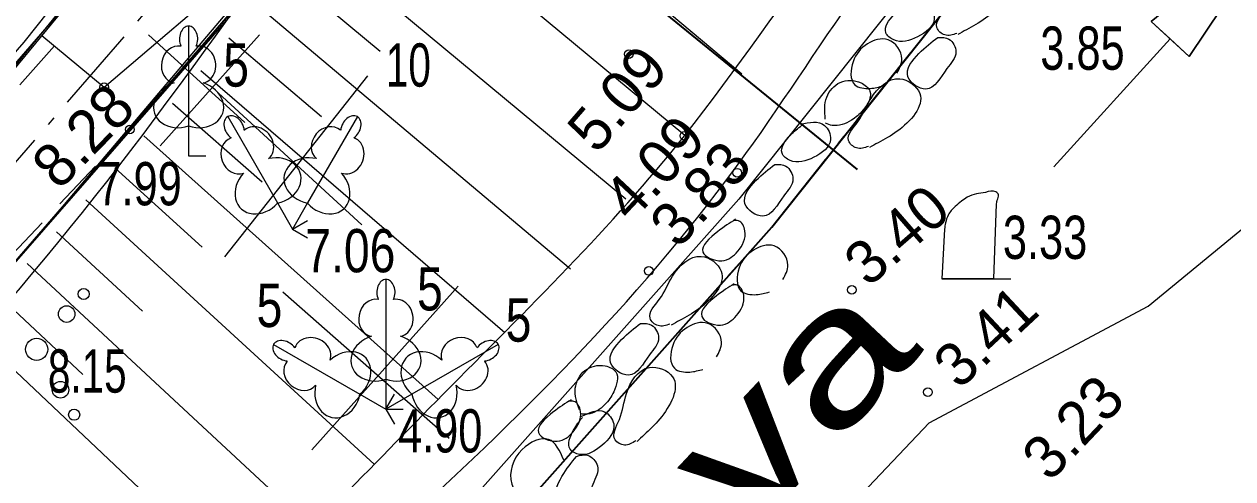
# Model space of a CAD drawing. Extents: x 514052 to 514314, y 297701 to 297876.
# Drawn here: x 514248.88 to 514262.86, y 297791.45 to 297796.71 of the extents above; entities that cross this region are included whole.
import ezdxf

# ---------------------------------------------------------------- set-up
doc = ezdxf.new("R2010")
doc.units = 0
doc.header["$LTSCALE"] = 0.2
doc.linetypes.add('DOT_DASHED', pattern=[7.7, 5, -1.2, 0.3, -1.2])
doc.linetypes.add('MEDIUM_DASHED', pattern=[4.5, 3, -1.5])
for name, color, linetype, lineweight in [('1', 7, 'Continuous', 13), ('19', 7, 'Continuous', 25), ('35', 7, 'Continuous', 25), ('4', 7, 'Continuous', 13), ('5', 7, 'Continuous', 13), ('55', 7, 'Continuous', 13), ('56', 7, 'Continuous', 13), ('6', 7, 'Continuous', 13), ('61', 7, 'Continuous', 13), ('62', 7, 'Continuous', 13), ('63', 7, 'Continuous', 13)]:
    doc.layers.add(name, color=color, linetype=linetype, lineweight=lineweight)
for name, color, linetype in [('12', 7, 'Continuous'), ('27', 7, 'Continuous'), ('8', 7, 'Continuous')]:
    doc.layers.add(name, color=color, linetype=linetype)

msp = doc.modelspace()

# ---------------------------------------------------------------- linework, layer by layer
at = {"layer": '1'}
for p, q in [((514253.484, 297799.238), (514257.177, 297796.134)), ((514252.844, 297798.47), (514256.52, 297795.422)), ((514252.206, 297797.701), (514255.837, 297794.686)), ((514251.886, 297797.316), (514252.993, 297796.394)), ((514251.565, 297796.933), (514255.194, 297793.878)), ((514251.243, 297796.55), (514252.317, 297795.641)), ((514250.918, 297796.17), (514254.438, 297793.143)), ((514250.59, 297795.792), (514251.63, 297794.884)), ((514250.26, 297795.418), (514253.663, 297792.368)), ((514249.925, 297795.046), (514250.935, 297794.13)), ((514249.588, 297794.676), (514252.926, 297791.62)), ((514249.25, 297794.308), (514250.245, 297793.391)), ((514248.911, 297793.941), (514252.207, 297790.881)), ((514248.57, 297793.575), (514249.554, 297792.656)), ((514248.228, 297793.211), (514251.49, 297790.135))]:
    msp.add_line(p, q, dxfattribs=at)
msp.add_spline([(514260.862, 297805.466), (514258.749, 297804.839), (514257.459, 297803.011), (514254.953, 297800.933), (514250.105, 297795.245), (514240.136, 297784.718), (514236.07, 297778.812), (514235.246, 297774.955), (514233.92, 297771.109), (514234.456, 297764.804)], degree=3, dxfattribs=at)
at = {"layer": '19', "lineweight": 13}
msp.add_spline([(514243.205, 297765.058), (514242.936, 297773.769), (514245.025, 297781.038), (514246.54, 297783.925), (514249.054, 297787.013), (514257.225, 297795.21), (514260.154, 297798.886), (514267.863, 297801.516), (514273.305, 297805.826), (514276.583, 297807.615)], degree=3, dxfattribs=at)
at = {"layer": '35'}
msp.add_lwpolyline([(514231.97, 297771.331), (514233.541, 297774.128), (514233.667, 297780.485), (514240.255, 297787.177), (514246.843, 297793.868), (514250.774, 297798.68), (514254.387, 297803.352), (514256.058, 297805.511), (514258.694, 297808.915), (514260.151, 297809.248), (514268.632, 297811.186)], dxfattribs=at)
at = {"layer": '35', "lineweight": 35}
msp.add_lwpolyline([(514271.3, 297810.152), (514259.606, 297807.499), (514252.681, 297798.474), (514245.829, 297790.57), (514238.515, 297783.139), (514236.323, 297779.764), (514235.19, 297775.821), (514235.133, 297773.758), (514233.372, 297770.559)], dxfattribs=at)
at = {"layer": '4'}
msp.add_line((514260.785, 297795.058), (514262.132, 297796.536), dxfattribs=at)
for points in [[(514263.48, 297798.014), (514262.354, 297796.334), (514261.911, 297796.738)], [(514262.132, 297796.536), (514262.354, 297796.334), (514263.48, 297798.014), (514261.911, 297796.738)]]:
    msp.add_lwpolyline(points, close=True, dxfattribs=at)
at = {"layer": '5'}
for p, q in [((514250.778, 297796.684), (514250.778, 297795.531)), ((514250.868, 297796.452), (514250.867, 297796.453)), ((514251.23, 297795.638), (514251.806, 297794.64)), ((514252.73, 297795.638), (514252.153, 297794.64)), ((514250.778, 297795.531), (514250.778, 297795.184)), ((514251.424, 297795.482), (514251.422, 297795.482)), ((514252.691, 297795.392), (514252.691, 297795.393)), ((514250.778, 297795.184), (514250.978, 297795.184)), ((514251.806, 297794.64), (514251.98, 297794.339)), ((514252.153, 297794.64), (514251.98, 297794.339)), ((514260.091, 297793.765), (514260.125, 297794.63)), ((514251.98, 297794.339), (514252.153, 297794.439)), ((514251.98, 297794.339), (514252.153, 297794.239)), ((514253.061, 297793.756), (514253.061, 297792.603)), ((514260.091, 297793.765), (514259.491, 297793.765)), ((514260.091, 297793.765), (514260.291, 297793.765)), ((514253.151, 297793.524), (514253.15, 297793.525)), ((514251.762, 297793.006), (514252.76, 297792.43)), ((514254.36, 297793.006), (514253.361, 297792.43)), ((514252.008, 297792.968), (514252.007, 297792.967)), ((514254.204, 297792.812), (514254.204, 297792.814)), ((514253.061, 297792.603), (514253.061, 297792.256)), ((514252.76, 297792.43), (514253.061, 297792.256)), ((514253.361, 297792.43), (514253.061, 297792.256)), ((514253.061, 297792.256), (514253.161, 297792.429)), ((514253.061, 297792.256), (514253.261, 297792.256)), ((514253.061, 297792.256), (514253.161, 297792.083))]:
    msp.add_line(p, q, dxfattribs=at)
msp.add_lwpolyline([(514259.522, 297794.338), (514259.491, 297793.765), (514259.791, 297793.765), (514260.091, 297793.765)], dxfattribs=at)
for centre, radius in [((514249.5639, 297793.5875), 0.064), ((514249.3675, 297793.3558), 0.096), ((514249.0199, 297792.9482), 0.128), ((514249.2964, 297792.4813), 0.096), ((514249.4539, 297792.192), 0.064)]:
    msp.add_circle(centre, radius, dxfattribs=at)
for centre, major_axis, ratio, start_param, end_param in [((514250.7784, 297796.5342), (0, -0.1499), 0.707107, 3.1453698, 5.2874846), ((514250.7775, 297796.5342), (0, -0.1499), 0.707107, 0.9957007, 3.1378155), ((514250.6497, 297796.2394), (-0.0387, -0.2124), 0.861323, 3.1415927, 6.2831853), ((514250.9062, 297796.2394), (0.0387, -0.2124), 0.861323, 6.2831853, 9.424778), ((514250.6884, 297795.7771), (0.3068, 0.0951), 0.814445, 1.5707963, 4.7520146), ((514250.8675, 297795.7771), (-0.3068, 0.0951), 0.814445, 1.5311707, 4.712389), ((514251.3053, 297795.5085), (0.075, -0.1298), 0.707107, 3.1453698, 5.2874846), ((514251.3046, 297795.5081), (0.075, -0.1298), 0.707107, 0.9957007, 3.1378155), ((514252.6553, 297795.5081), (-0.075, -0.1298), 0.707107, 3.1453698, 5.2874846), ((514252.6546, 297795.5085), (-0.075, -0.1298), 0.707107, 0.9957007, 3.1378155), ((514251.5635, 297795.3171), (0.1397, -0.1646), 0.861323, 6.2831853, 9.424778), ((514252.3964, 297795.3171), (-0.1397, -0.1646), 0.861323, 3.1415927, 6.2831853), ((514251.3412, 297795.1888), (0.0727, -0.2033), 0.861323, 3.1415927, 6.2831853), ((514252.6187, 297795.1888), (-0.0727, -0.2033), 0.861323, 6.2831853, 9.424778), ((514251.7611, 297794.8974), (-0.3133, -0.071), 0.814445, 1.5311707, 4.712389), ((514252.1988, 297794.8974), (0.3133, -0.071), 0.814445, 1.5707963, 4.7520146), ((514251.6059, 297794.8078), (0.2182, 0.2358), 0.814445, 1.5707963, 4.7520146), ((514252.354, 297794.8078), (-0.2182, 0.2358), 0.814445, 1.5311707, 4.712389), ((514253.0614, 297793.6062), (0, -0.1499), 0.707107, 3.1453698, 5.2874846), ((514253.0605, 297793.6062), (0, -0.1499), 0.707107, 0.9957007, 3.1378155), ((514253.1892, 297793.3114), (0.0387, -0.2124), 0.861323, 6.2831853, 9.424778), ((514252.9327, 297793.3114), (-0.0387, -0.2124), 0.861323, 3.1415927, 6.2831853), ((514251.892, 297792.9315), (0.1298, -0.075), 0.707107, 3.1453698, 5.2874846), ((514251.8916, 297792.9308), (0.1298, -0.075), 0.707107, 0.9957007, 3.1378155), ((514252.2113, 297792.8949), (0.2033, -0.0727), 0.861323, 6.2831853, 9.424778), ((514252.9714, 297792.8491), (0.3068, 0.0951), 0.814445, 1.5707963, 4.7520146), ((514253.1505, 297792.8491), (-0.3068, 0.0951), 0.814445, 1.5311707, 4.712389), ((514253.9106, 297792.8949), (-0.2033, -0.0727), 0.861323, 3.1415927, 6.2831853), ((514254.2303, 297792.9308), (-0.1298, -0.075), 0.707107, 3.1453698, 5.2874846), ((514254.2299, 297792.9315), (-0.1298, -0.075), 0.707107, 0.9957007, 3.1378155), ((514252.5923, 297792.6302), (-0.2358, -0.2182), 0.814445, 1.5311707, 4.712389), ((514253.5296, 297792.6302), (0.2358, -0.2182), 0.814445, 1.5707963, 4.7520146), ((514252.083, 297792.6726), (0.1646, -0.1397), 0.861323, 3.1415927, 6.2831853), ((514254.0389, 297792.6726), (-0.1646, -0.1397), 0.861323, 6.2831853, 9.424778), ((514252.5027, 297792.475), (0.071, 0.3133), 0.814445, 1.5707963, 4.7520146), ((514253.6192, 297792.475), (-0.071, 0.3133), 0.814445, 1.5311707, 4.712389)]:
    msp.add_ellipse(centre, major_axis=major_axis, ratio=ratio, start_param=start_param, end_param=end_param, dxfattribs=at)
msp.add_spline([(514260.125, 297794.63), (514260.129, 297794.661), (514260.132, 297794.672), (514260.147, 297794.734), (514260.117, 297794.769), (514259.995, 297794.763), (514259.891, 297794.745), (514259.785, 297794.706), (514259.72, 297794.662), (514259.645, 297794.598), (514259.565, 297794.5), (514259.534, 297794.411), (514259.522, 297794.337)], degree=3, dxfattribs=at)
at = {"layer": '55'}
for points in [[(514217.339, 297769.84), (514231.97, 297771.331), (514233.541, 297774.128), (514233.602, 297778.964), (514248.877, 297796.499), (514258.817, 297808.985), (514270.863, 297811.577), (514272.894, 297813.849)], [(514245.484, 297761.608), (514245.786, 297768.251), (514247.238, 297775.723), (514250.297, 297781.961), (514257.654, 297790.318), (514259.345, 297792.1), (514261.879, 297793.446), (514269.393, 297799.625), (514276.431, 297803.309), (514278.49, 297803.954), (514281.804, 297808.459), (514282.968, 297810.375)]]:
    msp.add_lwpolyline(points, dxfattribs=at)
at = {"layer": '56'}
msp.add_lwpolyline([(514249.079, 297796.575), (514249.802, 297795.978), (514251.44, 297797.376), (514252.508, 297798.584), (514251.401, 297799.459)], close=True, dxfattribs=at)
at = {"layer": '6'}
for centre in [(514255.87, 297796.3591), (514249.8019, 297795.9781), (514250.098, 297795.4881), (514256.513, 297795.4151), (514257.125, 297794.9901), (514256.1029, 297793.8541), (514258.4499, 297793.6351), (514259.3309, 297792.4531)]:
    msp.add_circle(centre, 0.05, dxfattribs=at)
at = {"layer": '61'}
msp.add_lwpolyline([(514246.843, 297793.868), (514250.081, 297797.789), (514258.694, 297808.915), (514270.983, 297811.723)], dxfattribs=at)
at = {"layer": '62'}
msp.add_spline([(514242.228, 297765.875), (514240.809, 297773.912), (514243.289, 297779.448), (514244.466, 297781.572), (514244.559, 297781.63), (514245.987, 297783.723), (514248.871, 297787.176), (514251.243, 297789.878), (514252.476, 297791.159), (514253.723, 297792.429), (514256.513, 297795.415), (514260.533, 297799.834), (514263.587, 297801.907), (514261.268, 297805.481)], degree=3, dxfattribs=at)
at = {"layer": '63', "lineweight": 35}
msp.add_line((514251.465, 297800.758), (514258.511, 297795.026), dxfattribs=at)
at = {"layer": '63'}
for p, q in [((514250.313, 297796.584), (514251.428, 297795.57)), ((514251.597, 297796.584), (514250.448, 297795.3)), ((514252.847, 297796.111), (514251.192, 297794.016)), ((514251.124, 297795.908), (514252.78, 297794.388)), ((514251.867, 297793.611), (514253.793, 297791.921)), ((514253.895, 297793.678), (514252.205, 297791.786))]:
    msp.add_line(p, q, dxfattribs=at)
for points in [[(514241.033, 297787.835), (514244.727, 297791.588), (514248.123, 297795.505), (514251.519, 297799.422), (514255.132, 297804.131), (514258.746, 297808.841), (514264.857, 297810.227), (514270.968, 297811.614), (514271.3, 297810.152), (514259.609, 297807.499), (514256.144, 297802.987), (514253.336, 297799.341), (514249.255, 297794.522), (514245.829, 297790.57)], [(514246.248, 297791.053), (514247.856, 297792.907), (514251.587, 297797.176), (514252.569, 297798.349), (514254.104, 297800.332), (514255.107, 297801.628), (514257.105, 297804.234), (514259.609, 297807.499), (514265.761, 297808.894), (514271.304, 297810.15), (514273.327, 297806.65), (514267.17, 297803.809), (514264.799, 297803.032), (514260.928, 297799.431), (514257.141, 297794.684), (514253.744, 297790.866)]]:
    msp.add_lwpolyline(points, dxfattribs=at)
at = {"layer": '63', "linetype": 'MEDIUM_DASHED'}
for points in [[(514231.583, 297765.652), (514232.855, 297769.107), (514235.126, 297775.062), (514235.802, 297779.27), (514240.035, 297784.801), (514250.098, 297795.488), (514254.893, 297801.043), (514257.448, 297803.118), (514259.485, 297807.223), (514261.814, 297808.455), (514265.145, 297808.86), (514272.105, 297811.112)], [(514249.225, 297796.455), (514239.453, 297785.495), (514234.344, 297779.635), (514234.008, 297775.04), (514233.159, 297771.888), (514231.647, 297770.296), (514228.019, 297768.169)]]:
    msp.add_lwpolyline(points, dxfattribs=at)
at = {"layer": '63', "linetype": 'DOT_DASHED', "lineweight": 25}
for points in [[(514271.134, 297810.883), (514259.176, 297808.17), (514252.1, 297798.948), (514245.278, 297791.079), (514237.927, 297783.611), (514235.633, 297780.079), (514234.443, 297775.937), (514234.388, 297773.96), (514232.332, 297770.225), (514229.92, 297766.887)], [(514241.744, 297765.925), (514242.057, 297774.207), (514242.797, 297776.707), (514244.225, 297779.218), (514245.964, 297781.323), (514250.712, 297786.706), (514257.523, 297794.362), (514261.299, 297799.094), (514264.423, 297802.109), (514265.043, 297802.596), (514265.222, 297802.656), (514267.352, 297803.342), (514273.537, 297806.201)]]:
    msp.add_lwpolyline(points, dxfattribs=at)
at = {"layer": '63', "lineweight": 35}
msp.add_lwpolyline([(514241.744, 297765.925), (514242.057, 297774.207), (514242.797, 297776.707), (514244.225, 297779.218), (514245.094, 297780.271), (514245.964, 297781.323), (514248.338, 297784.015), (514250.712, 297786.706), (514254.118, 297790.534), (514257.523, 297794.362), (514259.411, 297796.728), (514261.299, 297799.094), (514262.861, 297800.601), (514264.423, 297802.109), (514265.043, 297802.596), (514267.352, 297803.342), (514273.537, 297806.201)], dxfattribs=at)
msp.add_spline([(514235.586, 297788.069), (514238.834, 297789.344), (514246.139, 297795.966), (514248.394, 297799.596), (514253.835, 297808.327)], degree=3, dxfattribs=at)
at = {"layer": '63'}
for points in [[(514259.663, 297796.6), (514259.525, 297796.582), (514259.434, 297796.667), (514259.54, 297796.883), (514259.693, 297797.155), (514260.025, 297797.382), (514260.257, 297797.213), (514259.997, 297796.776), (514259.775, 297796.642), (514259.676, 297796.587)], [(514259.056, 297796.945), (514259.334, 297796.93), (514259.404, 297796.769), (514259.209, 297796.561), (514258.935, 297796.525), (514258.843, 297796.609), (514258.937, 297796.814), (514259.071, 297796.932)], [(514258.971, 297796.139), (514259.029, 297796.305), (514258.869, 297796.526), (514258.631, 297796.479), (514258.464, 297796.272), (514258.485, 297796.007), (514258.663, 297795.964), (514258.814, 297795.995)], [(514259.446, 297796.554), (514259.226, 297796.369), (514259.099, 297796.1), (514259.305, 297795.957), (514259.549, 297796.193), (514259.654, 297796.387), (514259.573, 297796.534), (514259.446, 297796.554)], [(514258.143, 297795.61), (514258.159, 297795.863), (514258.316, 297796.033), (514258.557, 297796.028), (514258.66, 297795.932), (514258.58, 297795.715), (514258.445, 297795.596), (514258.222, 297795.537), (514258.145, 297795.561)], [(514258.642, 297795.294), (514258.504, 297795.276), (514258.413, 297795.361), (514258.519, 297795.577), (514258.672, 297795.849), (514259.004, 297796.076), (514259.236, 297795.907), (514258.976, 297795.47), (514258.754, 297795.336), (514258.655, 297795.281)], [(514257.856, 297795.552), (514258.134, 297795.537), (514258.204, 297795.376), (514258.009, 297795.168), (514257.735, 297795.132), (514257.643, 297795.216), (514257.737, 297795.421), (514257.871, 297795.539)], [(514257.561, 297795.085), (514257.341, 297794.9), (514257.214, 297794.631), (514257.42, 297794.488), (514257.664, 297794.724), (514257.769, 297794.918), (514257.688, 297795.065), (514257.561, 297795.085)], [(514257.105, 297794.451), (514256.896, 297794.308), (514256.728, 297794.073), (514256.946, 297793.973), (514257.13, 297794.082), (514257.214, 297794.317), (514257.139, 297794.434), (514257.08, 297794.434)], [(514257.653, 297793.756), (514257.711, 297793.922), (514257.551, 297794.143), (514257.313, 297794.096), (514257.146, 297793.889), (514257.167, 297793.624), (514257.345, 297793.581), (514257.496, 297793.612)], [(514256.346, 297793.24), (514256.208, 297793.222), (514256.117, 297793.307), (514256.223, 297793.523), (514256.376, 297793.795), (514256.708, 297794.022), (514256.94, 297793.853), (514256.68, 297793.416), (514256.458, 297793.282), (514256.359, 297793.227)], [(514257.09, 297793.707), (514256.881, 297793.564), (514256.713, 297793.329), (514256.931, 297793.229), (514257.115, 297793.338), (514257.199, 297793.573), (514257.124, 297793.69), (514257.065, 297793.69)], [(514256.885, 297792.861), (514256.943, 297793.027), (514256.783, 297793.248), (514256.545, 297793.201), (514256.378, 297792.994), (514256.399, 297792.729), (514256.577, 297792.686), (514256.728, 297792.717)], [(514256.007, 297793.247), (514255.787, 297793.062), (514255.66, 297792.793), (514255.866, 297792.65), (514256.11, 297792.886), (514256.215, 297793.08), (514256.134, 297793.227), (514256.007, 297793.247)], [(514255.298, 297792.249), (514255.251, 297792.499), (514255.362, 297792.702), (514255.597, 297792.756), (514255.72, 297792.688), (514255.696, 297792.458), (514255.594, 297792.31), (514255.392, 297792.198), (514255.312, 297792.202)], [(514255.95, 297791.892), (514255.82, 297791.841), (514255.711, 297791.901), (514255.761, 297792.137), (514255.843, 297792.438), (514256.109, 297792.739), (514256.376, 297792.632), (514256.23, 297792.145), (514256.048, 297791.961), (514255.965, 297791.883)], [(514255.202, 297792.364), (514254.993, 297792.221), (514254.825, 297791.986), (514255.043, 297791.886), (514255.227, 297791.995), (514255.311, 297792.23), (514255.236, 297792.347), (514255.177, 297792.347)], [(514255.316, 297792.171), (514255.589, 297792.225), (514255.696, 297792.086), (514255.558, 297791.836), (514255.301, 297791.734), (514255.191, 297791.793), (514255.232, 297792.015), (514255.333, 297792.162)], [(514255.119, 297791.669), (514254.943, 297791.907), (514254.637, 297791.79), (514254.518, 297791.389), (514254.717, 297791.157), (514255.029, 297791.21)], [(514255.265, 297791.711), (514255.097, 297791.478), (514255.039, 297791.186), (514255.274, 297791.098), (514255.453, 297791.386), (514255.507, 297791.6), (514255.393, 297791.723), (514255.265, 297791.711)]]:
    msp.add_spline(points, degree=3, dxfattribs=at)

# ---------------------------------------------------------------- texts
at = {"layer": '12'}
for s, width, p in [(' 5', 0.8, (514251.03, 297795.985)), (' 10', 0.7, (514252.93, 297795.985)), (' 5', 0.8, (514253.272, 297793.398)), (' 5', 0.8, (514251.416, 297793.206)), (' 5', 0.8, (514254.297, 297793.037))]:
    msp.add_text(s, height=0.5, dxfattribs=dict(at, width=width)).set_placement(p)
at = {"layer": '27', "width": 1.4}
msp.add_text('upe Íekava', height=1.5, rotation=46.796, dxfattribs=at).set_placement((514249.884, 297782.926))
at = {"layer": '8'}
for s, width, p in [(' 3.85', 0.75, (514260.491, 297796.18)), (' 7.99', 0.75, (514249.584, 297794.613)), (' 3.33', 0.75, (514260.058, 297793.993)), (' 7.06', 0.8, (514251.98, 297793.839)), (' 8.15', 0.7, (514249.02, 297792.448)), (' 4.90', 0.75, (514253.061, 297791.756))]:
    msp.add_text(s, height=0.5, dxfattribs=dict(at, width=width)).set_placement(p)
for s, rotation, p in [(' 5.09', 49.117, (514255.379, 297795.053)), (' 8.28', 45.877, (514249.153, 297794.643)), (' 4.09', 46.86, (514255.771, 297794.268)), (' 3.83', 47.809, (514256.32, 297793.961)), (' 3.40', 40.947, (514258.501, 297793.534)), (' 3.41', 43.053, (514259.556, 297792.346)), (' 3.23', 46.533, (514260.613, 297791.269))]:
    msp.add_text(s, height=0.5, rotation=rotation, dxfattribs=at).set_placement(p)

doc.saveas('drawing.dxf')
